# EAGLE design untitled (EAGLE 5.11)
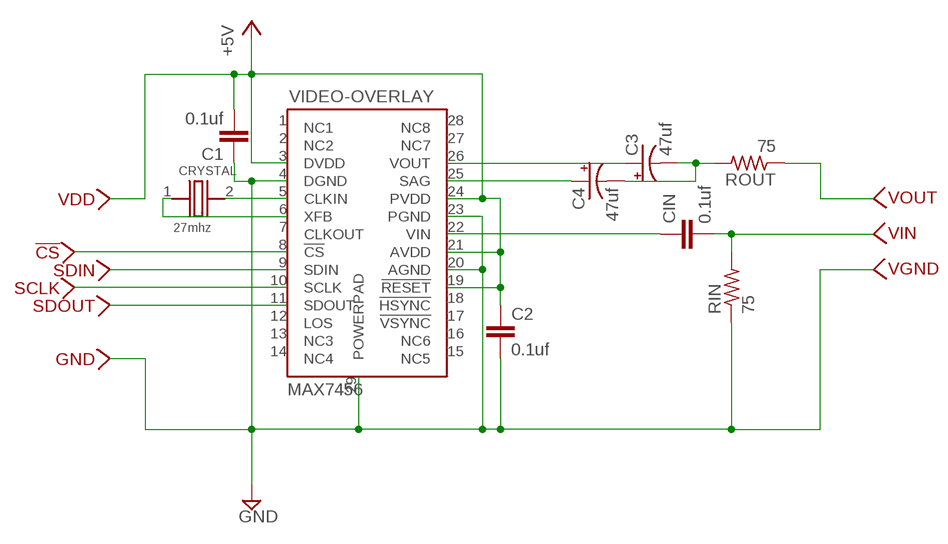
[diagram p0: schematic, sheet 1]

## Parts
!CS  WIREPAD-SMD-SMALL-NAMED  [WIREPAD-SMD-SMALL]
C1  0.1uf  C-EUC1206  [C1206]
C2  0.1uf  C-EUC1206  [C1206]
C3  47uf  CPOL-USSANYO_SMD_C6  [SANYO-OSCON_SMD_C6]
C4  47uf  CPOL-USSANYO_SMD_C6  [SANYO-OSCON_SMD_C6]
CIN  0.1uf  C-EUC1206  [C1206]
CRYSTAL  27mhz  CRYSTAL-1203  [CRYSTAL-1203]
GND  WIREPAD-SMD-SMALL-NAMED  [WIREPAD-SMD-SMALL]
RIN  75  R-US_R1210  [R1210]
ROUT  75  R-US_R1210  [R1210]
SCLK  WIREPAD-SMD-SMALL-NAMED  [WIREPAD-SMD-SMALL]
SDIN  WIREPAD-SMD-SMALL-NAMED  [WIREPAD-SMD-SMALL]
SDOUT  WIREPAD-SMD-SMALL-NAMED  [WIREPAD-SMD-SMALL]
VDD  WIREPAD-SMD-SMALL-NAMED  [WIREPAD-SMD-SMALL]
VGND  WIREPAD-SMD-SMALL-NAMED  [WIREPAD-SMD-SMALL]
VIDEO-OVERLAY  MAX7456  [TSSOP28-POWERPAD]
VIN  WIREPAD-SMD-SMALL-NAMED  [WIREPAD-SMD-SMALL]
VOUT  WIREPAD-SMD-SMALL-NAMED  [WIREPAD-SMD-SMALL]

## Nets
+5V: C1.2 C2.1 VDD.1 VIDEO-OVERLAY.3(DVDD) VIDEO-OVERLAY.19(!RESET) VIDEO-OVERLAY.21(AVDD) VIDEO-OVERLAY.24(PVDD)
GND: C1.1 C2.2 GND.1 RIN.1 VGND.1 VIDEO-OVERLAY.4(DGND) VIDEO-OVERLAY.20(AGND) VIDEO-OVERLAY.23(PGND) VIDEO-OVERLAY.29(POWERPAD)
N$1: CRYSTAL.2 VIDEO-OVERLAY.5(CLKIN)
N$2: CRYSTAL.1 VIDEO-OVERLAY.6(XFB)
N$3: SDOUT.1 VIDEO-OVERLAY.11(SDOUT)
N$4: SCLK.1 VIDEO-OVERLAY.10(SCLK)
N$5: SDIN.1 VIDEO-OVERLAY.9(SDIN)
N$6: !CS.1 VIDEO-OVERLAY.8(!CS)
N$7: C4.+ VIDEO-OVERLAY.25(SAG)
N$8: C3.- C4.- ROUT.2
N$9: C3.+ VIDEO-OVERLAY.26(VOUT)
N$10: CIN.1 VIDEO-OVERLAY.22(VIN)
N$11: CIN.2 RIN.2 VIN.1
N$12: ROUT.1 VOUT.1
Unconnected: VIDEO-OVERLAY.1(NC1) VIDEO-OVERLAY.2(NC2) VIDEO-OVERLAY.7(CLKOUT) VIDEO-OVERLAY.12(LOS) VIDEO-OVERLAY.13(NC3) VIDEO-OVERLAY.14(NC4) VIDEO-OVERLAY.15(NC5) VIDEO-OVERLAY.16(NC6) VIDEO-OVERLAY.17(!VSYNC) VIDEO-OVERLAY.18(!HSYNC) VIDEO-OVERLAY.27(NC7) VIDEO-OVERLAY.28(NC8)

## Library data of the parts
!CS GND SCLK SDIN SDOUT VDD VGND VIN VOUT = trl:WIREPAD-SMD-SMALL-NAMED
C1 C2 CIN = rcl:C-EU: CAPACITOR, European symbol
C3 C4 = rcl:CPOL-US: POLARIZED CAPACITOR, American symbol
CRYSTAL = trl:CRYSTAL-1203
RIN ROUT = resistor:R-US_: RESISTOR, American symbol
VIDEO-OVERLAY = trl:MAX7456

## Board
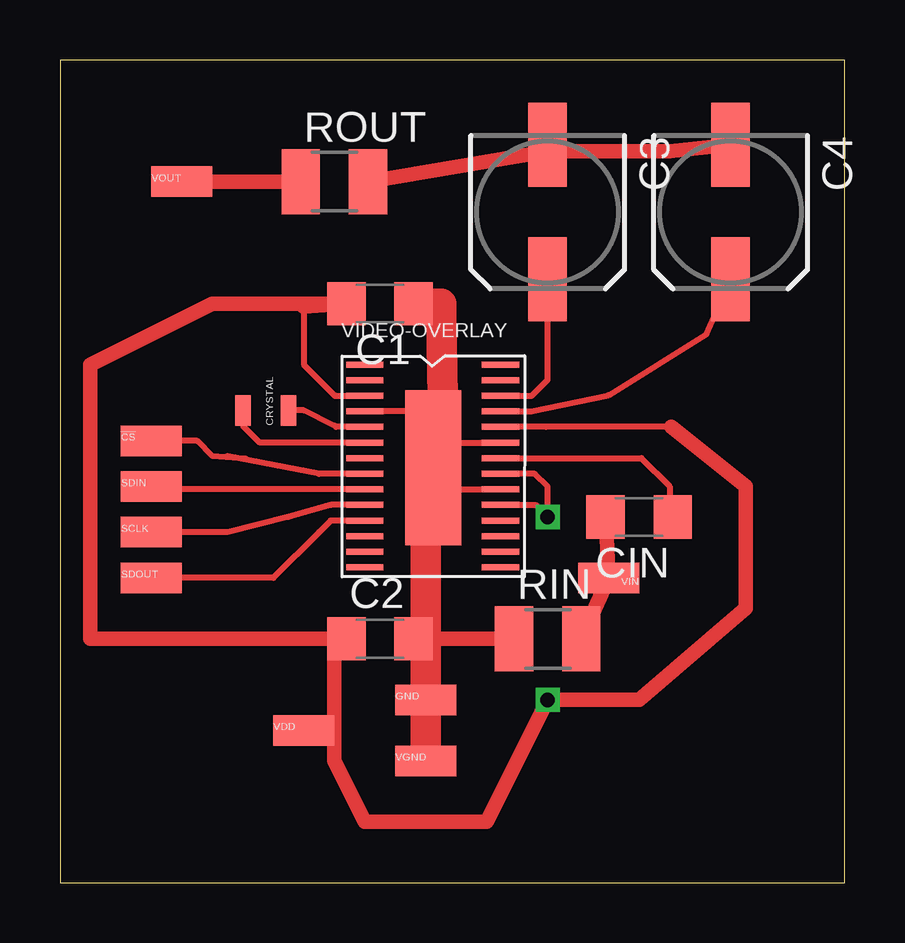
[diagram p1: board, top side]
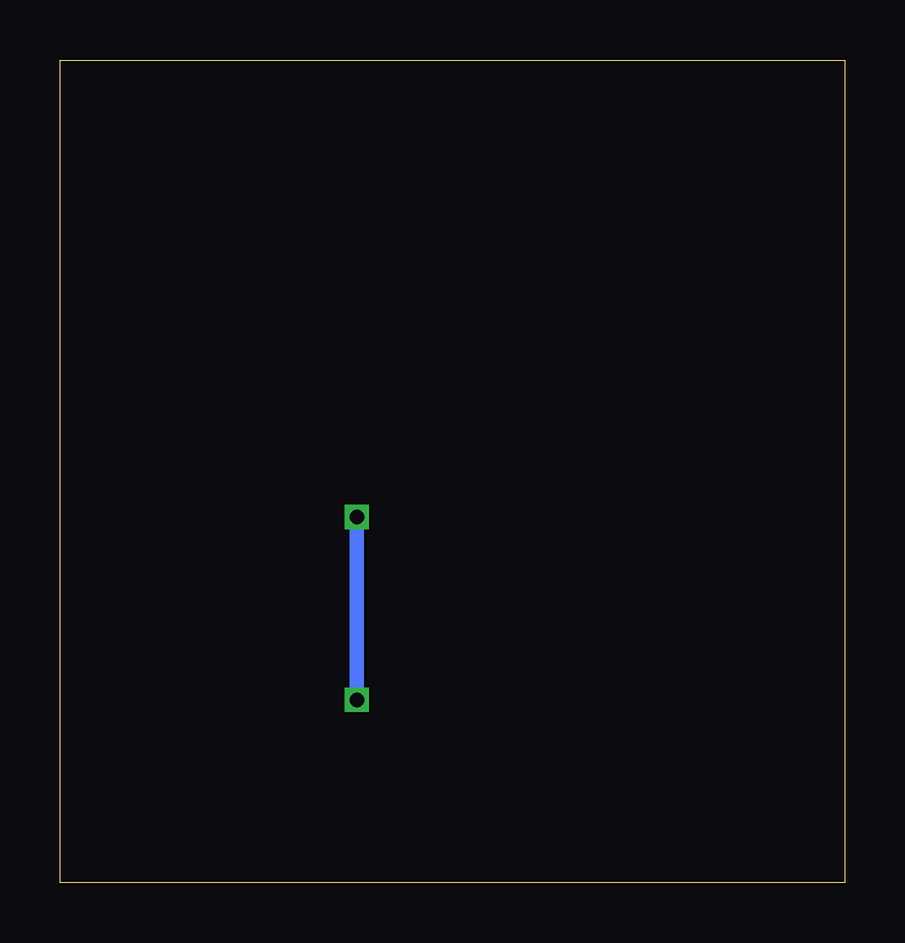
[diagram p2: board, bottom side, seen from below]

Size 32.69 x 34.28 mm. Coordinates in mm from the lower left corner, seen from the top.
Outline: 0,0 32.69,0 32.69,34.28 0,34.28 0,0
Copper layers (1*16): Top 0.035mm / dielectric 1.5mm / Bottom 0.035mm
Design rules "default": minimum track width 10mil, minimum drill 24mil, track to track 8mil, track to pad 8mil, pad to pad 8mil, via to via 8mil, smd to smd 8mil, copper to edge 40mil, drill to drill 8mil, minimum pad ring 10mil, minimum via ring 8mil, stop-mask expansion 4mil, vias tented up to drill 0mil, thermal gap 10mil

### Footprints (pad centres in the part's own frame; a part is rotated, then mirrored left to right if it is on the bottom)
WIREPAD-SMD-SMALL = smd 2.54 x 1.27: 1 0,0
C1206 = smd 1.6 x 1.8: 1 -1.4,0; 2 1.4,0
SANYO-OSCON_SMD_C6 = smd 3.5 x 1.6: + 2.8,0; - -2.8,0
CRYSTAL-1203 = smd 0.635 x 1.27: 1 -1.27,0; 2 0.635,0
R1210 = smd 1.6 x 2.7: 1 -1.4,0; 2 1.4,0
TSSOP28-POWERPAD = smd 0.25 x 1.55: 1 -3.81,-2.54; 2 -3.16,-2.54; 3 -2.51,-2.54; 4 -1.86,-2.54; 5 -1.21,-2.54; 6 -0.56,-2.54; 7 0.09,-2.54; 8 0.74,-2.54; 9 1.39,-2.54; 10 2.04,-2.54; 11 2.69,-2.54; 12 3.34,-2.54; 13 3.99,-2.54; 14 4.64,-2.54; 15 4.64,3.11; 16 3.99,3.11; 17 3.34,3.11; 18 2.69,3.11; 19 2.04,3.11; 20 1.39,3.11; 21 0.74,3.11; 22 0.09,3.11; 23 -0.56,3.11; 24 -1.21,3.11; 25 -1.86,3.11; 26 -2.51,3.11; 27 -3.16,3.11; 28 -3.81,3.11 | smd 6.46 x 2.35: 29 0.49,0.31

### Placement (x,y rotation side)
!CS  3.81,18.41 0 top
C1  13.34,24.13 180 top
C2  13.34,10.16 0 top
C3  20.32,27.94 270 top
C4  27.94,27.94 270 top
CIN  24.13,15.24 180 top
CRYSTAL  8.89,19.68 0 top
GND  15.24,7.62 0 top
RIN  20.32,10.16 0 top
ROUT  11.43,29.21 0 top
SCLK  3.81,14.61 0 top
SDIN  3.81,16.51 0 top
SDOUT  3.81,12.7 0 top
VDD  10.16,6.35 0 top
VGND  15.24,5.08 0 top
VIDEO-OVERLAY  15.24,17.78 270 top
VIN  22.86,12.7 180 top
VOUT  5.08,29.21 0 top

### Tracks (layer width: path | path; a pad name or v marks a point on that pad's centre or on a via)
+5V  (via drill 0.6)
  Top 0.254: 11.43,6.35 VDD.1 | 11.43,10.16 C2.1 | 11.43,10.16 C2.1 | 11.43,10.16 C2.1 | 11.43,10.16 C2.1 | VIDEO-OVERLAY.3 11.46,20.29 11.43,20.32 10.16,21.59 10.16,22.86 10.16,24 | VIDEO-OVERLAY.19 19.82,15.74 v20.32,15.24 | 19.79,17.04 VIDEO-OVERLAY.21 19.79,17.04 | 20.32,16.51 19.79,17.04 | v20.32,15.24 20.32,16.51 | 20.32,16.51 19.79,17.04 | v20.32,15.24 20.32,16.51 | VIDEO-OVERLAY.24 20.26,18.99 25.46,18.99
  Top 0.61: 10.16,24 C1.2 6.35,24.13 1.27,21.59 1.27,10.16 11.43,10.16 11.43,6.35 11.43,5.08 12.7,2.54 17.78,2.54 19.05,5.08 v20.32,7.62 24.13,7.62 28.57,11.43 28.57,16.51 25.46,18.99
  Bottom 0.61: v20.32,15.24 v20.32,7.62
GND
  Top 0.254: VIDEO-OVERLAY.4 14.65,19.64 15.24,19.05 15.24,17.78 | 15.24,17.78 15.24,17.6 VIDEO-OVERLAY.29 16.33,16.51 16.51,16.51 16.63,16.39 VIDEO-OVERLAY.20 | 15.24,17.78 16,17.02 | VIDEO-OVERLAY.23 15.8,18.34 15.24,17.78
  Top 0.61: 15.24,10.16 RIN.1
  Top 1.016: C2.2 15.24,10.16
  Top 1.27: 16,17.02 15.88,23.5 15.88,24.13 C1.1 | 15.24,17.78 15.24,10.16 GND.1 VGND.1
N$1
  Top 0.254: VIDEO-OVERLAY.5 11.49,18.99 11.43,19.05 10.16,19.68 CRYSTAL.2
N$2
  Top 0.254: VIDEO-OVERLAY.6 8.33,18.34 7.62,19.05 CRYSTAL.1
N$3
  Top 0.254: VIDEO-OVERLAY.11 11.28,15.09 10.79,14.61 8.89,12.7 SDOUT.1
N$4
  Top 0.254: VIDEO-OVERLAY.10 11.29,15.74 9.53,15.24 6.99,14.61 5.71,14.61 SCLK.1
N$5
  Top 0.254: VIDEO-OVERLAY.9 3.93,16.39 SDIN.1
N$6
  Top 0.254: VIDEO-OVERLAY.8 10.79,17.04 6.99,17.78 7.72,17.68 6.35,17.78 5.71,18.41 !CS.1
N$7
  Top 0.254: VIDEO-OVERLAY.25 19.64,19.64 22.86,20.32 26.93,22.86 C4.+
N$8
  Top 0.254: C3.- 20.32,30.48
  Top 0.61: ROUT.2 20.32,30.48 25.4,30.48 C4.-
N$9
  Top 0.254: VIDEO-OVERLAY.26 19.66,20.29 20.32,20.95 20.32,23.5 19.95,24.77 C3.+
N$10
  Top 0.254: VIDEO-OVERLAY.22 24.22,17.69 25.4,16.51 25.4,15.37 CIN.1
N$11
  Top 0.254: VIN.1 22.86,12.57
  Top 0.61: RIN.2 VIN.1 | 22.86,12.57 CIN.2
N$12
  Top 0.254: ROUT.1 10.16,29.21 | ROUT.1 10.16,29.21 | 10.16,29.21 ROUT.1 | ROUT.1 10.16,29.21
  Top 0.61: VOUT.1 ROUT.1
